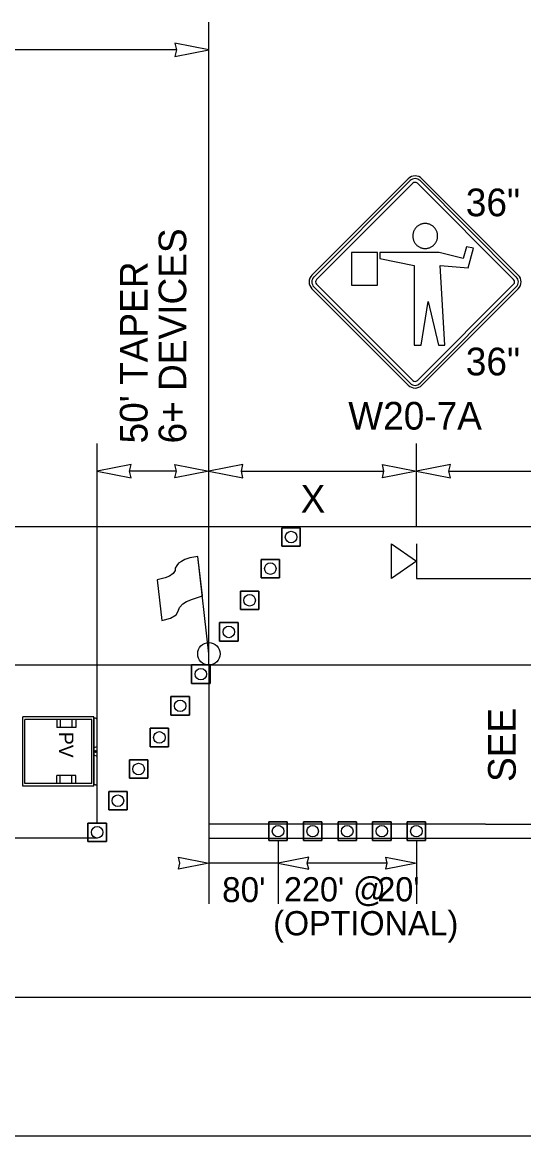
# Model space of a CAD drawing. Extents: x 99999.1 to 100095.7, y 99995 to 100010.7.
# Drawn here: x 100050.933 to 100052.384, y 100005.732 to 100008.949 of the extents above; entities that cross this region are included whole.
import ezdxf

# ---------------------------------------------------------------- set-up
doc = ezdxf.new("R2010")
doc.units = 0
for name, color, linetype in [('RD_ED_ShoulderPavedEdge', 7, 'Continuous'), ('RD_MK_LineDblYellowCenter', 7, 'Continuous'), ('RD_MK_LineEdgeWhite', 7, 'Continuous'), ('RD_MK_LineNoPass', 7, 'Continuous'), ('RD_MK_LineSkipCenter', 7, 'Continuous'), ('TR_SN_ConstructionSigns', 7, 'Continuous'), ('TR_WZ_FlaggingStation', 7, 'Continuous'), ('TR_WZ_PortableSignMountBlk-Org', 7, 'Continuous'), ('TR_WZ_ProtectiveVehicle', 7, 'Continuous'), ('TR_WZ_TrafficCone', 7, 'Continuous'), ('TR_WZ_WorkZoneDetails', 7, 'Continuous'), ('TR_WZ_WorkZoneTextCurrent', 7, 'Continuous')]:
    doc.layers.add(name, color=color, linetype=linetype)

msp = doc.modelspace()

# ---------------------------------------------------------------- linework, layer by layer
at = {"layer": 'RD_ED_ShoulderPavedEdge'}
for p, q in [((100040.1076, 100007.4923), (100055.6424, 100007.4923)), ((100040.1076, 100005.7323), (100055.6424, 100005.7323))]:
    msp.add_line(p, q, dxfattribs=at)
at = {"layer": 'RD_MK_LineDblYellowCenter'}
for p, q in [((100052.2733, 100006.6323), (100055.6631, 100006.6323)), ((100052.2733, 100006.5923), (100055.6218, 100006.5923))]:
    msp.add_line(p, q, dxfattribs=at)
at = {"layer": 'RD_MK_LineEdgeWhite'}
for p, q in [((100040.1076, 100007.0923), (100055.6424, 100007.0923)), ((100040.1076, 100006.1323), (100055.6424, 100006.1323))]:
    msp.add_line(p, q, dxfattribs=at)
at = {"layer": 'RD_MK_LineNoPass'}
msp.add_line((100051.4733, 100006.5923), (100052.2733, 100006.5923), dxfattribs=at)
at = {"layer": 'RD_MK_LineSkipCenter'}
for points in [[(100052.2733, 100006.6323), (100051.4733, 100006.6323)], [(100051.15, 100006.5923), (100043.4767, 100006.5923)]]:
    msp.add_lwpolyline(points, dxfattribs=at)
at = {"layer": 'TR_SN_ConstructionSigns'}
for p, q in [((100052.0497, 100008.4972), (100051.7713, 100008.2188)), ((100052.3679, 100008.2188), (100052.0895, 100008.4972)), ((100052.0552, 100008.4917), (100051.7768, 100008.2132)), ((100051.7845, 100008.2055), (100052.063, 100008.4839)), ((100052.0762, 100008.4839), (100052.3546, 100008.2055)), ((100052.3624, 100008.2132), (100052.0839, 100008.4917)), ((100052.0921, 100008.367), (100052.0902, 100008.3666)), ((100052.094, 100008.3673), (100052.0921, 100008.367)), ((100052.0959, 100008.3675), (100052.094, 100008.3673)), ((100052.0978, 100008.3676), (100052.0959, 100008.3675)), ((100052.0997, 100008.3676), (100052.0978, 100008.3676)), ((100052.1016, 100008.3675), (100052.0997, 100008.3676)), ((100052.1036, 100008.3673), (100052.1016, 100008.3675)), ((100052.1054, 100008.367), (100052.1036, 100008.3673)), ((100052.1073, 100008.3666), (100052.1054, 100008.367)), ((100052.063, 100008.3354), (100052.0628, 100008.3335)), ((100052.0632, 100008.3373), (100052.063, 100008.3354)), ((100052.0636, 100008.3392), (100052.0632, 100008.3373)), ((100052.064, 100008.3411), (100052.0636, 100008.3392)), ((100052.0646, 100008.3429), (100052.064, 100008.3411)), ((100052.0652, 100008.3447), (100052.0646, 100008.3429)), ((100052.066, 100008.3465), (100052.0652, 100008.3447)), ((100052.0668, 100008.3482), (100052.066, 100008.3465)), ((100052.0677, 100008.3499), (100052.0668, 100008.3482)), ((100052.0688, 100008.3516), (100052.0677, 100008.3499)), ((100052.0698, 100008.3531), (100052.0688, 100008.3516)), ((100052.071, 100008.3546), (100052.0698, 100008.3531)), ((100052.0723, 100008.3561), (100052.071, 100008.3546)), ((100052.0737, 100008.3574), (100052.0723, 100008.3561)), ((100052.075, 100008.3587), (100052.0737, 100008.3574)), ((100052.0765, 100008.3599), (100052.075, 100008.3587)), ((100052.078, 100008.3611), (100052.0765, 100008.3599)), ((100052.0797, 100008.3621), (100052.078, 100008.3611)), ((100052.0813, 100008.3631), (100052.0797, 100008.3621)), ((100052.083, 100008.364), (100052.0813, 100008.3631)), ((100052.0847, 100008.3648), (100052.083, 100008.364)), ((100052.0865, 100008.3655), (100052.0847, 100008.3648)), ((100052.0884, 100008.3661), (100052.0865, 100008.3655)), ((100052.0902, 100008.3666), (100052.0884, 100008.3661)), ((100052.1091, 100008.3661), (100052.1073, 100008.3666)), ((100052.111, 100008.3655), (100052.1091, 100008.3661)), ((100052.1128, 100008.3648), (100052.111, 100008.3655)), ((100052.1145, 100008.364), (100052.1128, 100008.3648)), ((100052.1162, 100008.3631), (100052.1145, 100008.364)), ((100052.1179, 100008.3621), (100052.1162, 100008.3631)), ((100052.1195, 100008.3611), (100052.1179, 100008.3621)), ((100052.121, 100008.3599), (100052.1195, 100008.3611)), ((100052.1225, 100008.3587), (100052.121, 100008.3599)), ((100052.1239, 100008.3574), (100052.1225, 100008.3587)), ((100052.1252, 100008.3561), (100052.1239, 100008.3574)), ((100052.1265, 100008.3546), (100052.1252, 100008.3561)), ((100052.1276, 100008.3531), (100052.1265, 100008.3546)), ((100052.1288, 100008.3516), (100052.1276, 100008.3531)), ((100052.1298, 100008.3499), (100052.1288, 100008.3516)), ((100052.1307, 100008.3482), (100052.1298, 100008.3499)), ((100052.1315, 100008.3465), (100052.1307, 100008.3482)), ((100052.1323, 100008.3447), (100052.1315, 100008.3465)), ((100052.133, 100008.3429), (100052.1323, 100008.3447)), ((100052.1335, 100008.3411), (100052.133, 100008.3429)), ((100052.134, 100008.3392), (100052.1335, 100008.3411)), ((100052.1343, 100008.3373), (100052.134, 100008.3392)), ((100052.1346, 100008.3354), (100052.1343, 100008.3373)), ((100052.1347, 100008.3335), (100052.1346, 100008.3354)), ((100052.0628, 100008.3335), (100052.0628, 100008.3316)), ((100052.0628, 100008.3316), (100052.0628, 100008.3297)), ((100052.0628, 100008.3297), (100052.063, 100008.3278)), ((100052.063, 100008.3278), (100052.0632, 100008.3259)), ((100052.0632, 100008.3259), (100052.0636, 100008.324)), ((100052.0636, 100008.324), (100052.064, 100008.3221)), ((100052.064, 100008.3221), (100052.0646, 100008.3203)), ((100052.0646, 100008.3203), (100052.0652, 100008.3185)), ((100052.0652, 100008.3185), (100052.066, 100008.3167)), ((100052.066, 100008.3167), (100052.0668, 100008.315)), ((100052.0668, 100008.315), (100052.0677, 100008.3133)), ((100052.0677, 100008.3133), (100052.0688, 100008.3117)), ((100052.0688, 100008.3117), (100052.0698, 100008.3101)), ((100052.0698, 100008.3101), (100052.071, 100008.3086)), ((100052.071, 100008.3086), (100052.0723, 100008.3072)), ((100052.0723, 100008.3072), (100052.0737, 100008.3058)), ((100052.0737, 100008.3058), (100052.075, 100008.3045)), ((100052.075, 100008.3045), (100052.0765, 100008.3033)), ((100052.0765, 100008.3033), (100052.078, 100008.3021)), ((100052.1195, 100008.3021), (100052.121, 100008.3033)), ((100052.121, 100008.3033), (100052.1225, 100008.3045)), ((100052.1225, 100008.3045), (100052.1239, 100008.3058)), ((100052.1239, 100008.3058), (100052.1252, 100008.3072)), ((100052.1252, 100008.3072), (100052.1265, 100008.3086)), ((100052.1265, 100008.3086), (100052.1276, 100008.3101)), ((100052.1276, 100008.3101), (100052.1288, 100008.3117)), ((100052.1288, 100008.3117), (100052.1298, 100008.3133)), ((100052.1298, 100008.3133), (100052.1307, 100008.315)), ((100052.1307, 100008.315), (100052.1315, 100008.3167)), ((100052.1315, 100008.3167), (100052.1323, 100008.3185)), ((100052.1323, 100008.3185), (100052.133, 100008.3203)), ((100052.133, 100008.3203), (100052.1335, 100008.3221)), ((100052.1335, 100008.3221), (100052.134, 100008.324)), ((100052.134, 100008.324), (100052.1343, 100008.3259)), ((100052.1343, 100008.3259), (100052.1346, 100008.3278)), ((100052.1346, 100008.3278), (100052.1347, 100008.3297)), ((100052.1348, 100008.3316), (100052.1347, 100008.3335)), ((100052.1347, 100008.3297), (100052.1348, 100008.3316)), ((100051.8853, 100008.2843), (100051.8853, 100008.1896)), ((100051.9607, 100008.2843), (100051.8853, 100008.2843)), ((100051.9607, 100008.1896), (100051.9607, 100008.2843)), ((100052.139, 100008.2843), (100051.9677, 100008.2843)), ((100051.9677, 100008.2843), (100051.9677, 100008.2662)), ((100052.078, 100008.3021), (100052.0797, 100008.3011)), ((100052.0797, 100008.3011), (100052.0813, 100008.3001)), ((100052.0813, 100008.3001), (100052.083, 100008.2992)), ((100052.083, 100008.2992), (100052.0847, 100008.2984)), ((100052.0847, 100008.2984), (100052.0865, 100008.2977)), ((100052.0865, 100008.2977), (100052.0884, 100008.2971)), ((100052.0884, 100008.2971), (100052.0902, 100008.2966)), ((100052.0902, 100008.2966), (100052.0921, 100008.2962)), ((100052.0921, 100008.2962), (100052.094, 100008.2959)), ((100052.094, 100008.2959), (100052.0959, 100008.2957)), ((100052.0959, 100008.2957), (100052.0978, 100008.2956)), ((100052.0978, 100008.2956), (100052.0997, 100008.2956)), ((100052.0997, 100008.2956), (100052.1016, 100008.2957)), ((100052.1016, 100008.2957), (100052.1036, 100008.2959)), ((100052.1036, 100008.2959), (100052.1054, 100008.2962)), ((100052.1054, 100008.2962), (100052.1073, 100008.2966)), ((100052.1073, 100008.2966), (100052.1091, 100008.2971)), ((100052.1091, 100008.2971), (100052.111, 100008.2977)), ((100052.111, 100008.2977), (100052.1128, 100008.2984)), ((100052.1128, 100008.2984), (100052.1145, 100008.2992)), ((100052.1145, 100008.2992), (100052.1162, 100008.3001)), ((100052.1162, 100008.3001), (100052.1179, 100008.3011)), ((100052.1179, 100008.3011), (100052.1195, 100008.3021)), ((100052.2086, 100008.2671), (100052.139, 100008.2843)), ((100052.2183, 100008.3), (100052.2086, 100008.2671)), ((100052.2382, 100008.2964), (100052.2183, 100008.3)), ((100052.2232, 100008.2396), (100052.2382, 100008.2964)), ((100051.9677, 100008.2662), (100052.0672, 100008.2464)), ((100052.0672, 100008.2464), (100052.0672, 100008.0161)), ((100052.1553, 100008.0161), (100052.1422, 100008.2465)), ((100052.1422, 100008.2465), (100052.2232, 100008.2396)), ((100051.7713, 100008.179), (100052.0497, 100007.9006)), ((100051.7768, 100008.1845), (100052.0552, 100007.9061)), ((100052.063, 100007.9138), (100051.7845, 100008.1923)), ((100051.8853, 100008.1896), (100051.9607, 100008.1896)), ((100052.3546, 100008.1923), (100052.0762, 100007.9138)), ((100052.0839, 100007.9061), (100052.3624, 100008.1845)), ((100052.0895, 100007.9006), (100052.3679, 100008.179)), ((100052.0874, 100008.0161), (100052.107, 100008.1428)), ((100052.107, 100008.1428), (100052.1373, 100008.0161)), ((100052.0672, 100008.0161), (100052.0874, 100008.0161)), ((100052.1373, 100008.0161), (100052.1553, 100008.0161))]:
    msp.add_line(p, q, dxfattribs=at)
for centre, radius, start, end in [((100052.0696, 100008.4773), 0.0281, 45, 135), ((100052.0696, 100008.4773), 0.0203, 45, 135), ((100052.0696, 100008.4773), 0.00937, 45, 135), ((100051.7912, 100008.1989), 0.0281, 135, 225), ((100051.7912, 100008.1989), 0.0203, 135, 225), ((100052.348, 100008.1989), 0.0203, 315, 45), ((100052.348, 100008.1989), 0.0281, 315, 45), ((100051.7912, 100008.1989), 0.00937, 135, 225), ((100052.348, 100008.1989), 0.00937, 315, 45), ((100052.0696, 100007.9205), 0.0281, 225, 315), ((100052.0696, 100007.9205), 0.0203, 225, 315), ((100052.0696, 100007.9205), 0.00937, 225, 315)]:
    msp.add_arc(centre, radius, start, end, dxfattribs=at)
at = {"layer": 'TR_WZ_FlaggingStation'}
for p, q in [((100051.4543, 100007.2917), (100051.4413, 100007.4061)), ((100051.4733, 100007.1248), (100051.4413, 100007.4058)), ((100051.3233, 100007.3383), (100051.3366, 100007.2211)), ((100051.4543, 100007.2917), (100051.4543, 100007.2917))]:
    msp.add_line(p, q, dxfattribs=at)
for points in [[(100051.4413, 100007.4061), (100051.4355, 100007.4048), (100051.4177, 100007.4014), (100051.4039, 100007.3972), (100051.3942, 100007.3911), (100051.3857, 100007.3864), (100051.38, 100007.3796), (100051.3757, 100007.3717), (100051.3752, 100007.3655), (100051.3698, 100007.3563), (100051.359, 100007.3489), (100051.3466, 100007.3437), (100051.3233, 100007.3383)], [(100051.3366, 100007.2211), (100051.3448, 100007.2225), (100051.3624, 100007.2271), (100051.3781, 100007.2376), (100051.3846, 100007.2482), (100051.3885, 100007.2585), (100051.3976, 100007.2694), (100051.4086, 100007.2756), (100051.4259, 100007.2827), (100051.4543, 100007.2917)]]:
    msp.add_lwpolyline(points, dxfattribs=at)
msp.add_circle((100051.4733, 100007.1248), 0.0325, dxfattribs=at)
at = {"layer": 'TR_WZ_PortableSignMountBlk-Org'}
msp.add_line((100052.0733, 100007.4422), (100052.0733, 100007.3422), dxfattribs=at)
msp.add_lwpolyline([(100052.0733, 100007.3923), (100052.0015, 100007.3422), (100052.0015, 100007.4422)], close=True, dxfattribs=at)
at = {"layer": 'TR_WZ_ProtectiveVehicle'}
for p, q in [((100051.1404, 100006.9423), (100050.9347, 100006.9423)), ((100050.9347, 100006.7423), (100050.9347, 100006.9423)), ((100051.1346, 100006.9344), (100050.9405, 100006.9344)), ((100050.9405, 100006.7503), (100050.9405, 100006.9344)), ((100051.0332, 100006.9344), (100051.0332, 100006.9113)), ((100051.0432, 100006.9344), (100051.0432, 100006.9113)), ((100051.0772, 100006.9344), (100051.0772, 100006.9113)), ((100051.0882, 100006.9344), (100051.0882, 100006.9113)), ((100051.1346, 100006.7503), (100051.1346, 100006.9344)), ((100051.1404, 100006.7423), (100051.1404, 100006.9423)), ((100051.1456, 100006.939), (100051.1411, 100006.939)), ((100051.1411, 100006.7456), (100051.1411, 100006.939)), ((100051.15, 100006.7517), (100051.15, 100006.9329)), ((100051.0882, 100006.9113), (100051.0332, 100006.9113)), ((100051.15, 100006.8564), (100051.1411, 100006.8527)), ((100051.15, 100006.8282), (100051.1411, 100006.832)), ((100051.1476, 100006.8423), (100051.1435, 100006.8423)), ((100051.1456, 100006.8395), (100051.1456, 100006.8451)), ((100051.0882, 100006.7733), (100051.0332, 100006.7733)), ((100051.0332, 100006.7503), (100051.0332, 100006.7733)), ((100051.0432, 100006.7503), (100051.0432, 100006.7733)), ((100051.0772, 100006.7503), (100051.0772, 100006.7733)), ((100051.0882, 100006.7503), (100051.0882, 100006.7733)), ((100051.1404, 100006.7423), (100050.9347, 100006.7423)), ((100051.1346, 100006.7503), (100050.9405, 100006.7503)), ((100051.1456, 100006.7456), (100051.1411, 100006.7456))]:
    msp.add_line(p, q, dxfattribs=at)
for centre, major_axis, start_param, end_param in [((100051.1456, 100006.9329), (0, 0.0061), 4.712389, 6.283185), ((100051.1456, 100006.7517), (0, -0.0061), 6.283185, 7.853982)]:
    msp.add_ellipse(centre, major_axis=major_axis, ratio=0.73155, start_param=start_param, end_param=end_param, dxfattribs=at)
msp.add_ellipse((100051.1456, 100006.8423), major_axis=(0, 0.00282), ratio=0.73155, dxfattribs=at)
at = {"layer": 'TR_WZ_TrafficCone'}
for points in [[(100051.6843, 100007.4886), (100051.7376, 100007.4886), (100051.7376, 100007.4352), (100051.6843, 100007.4352), (100051.6843, 100007.4886)], [(100051.6843, 100007.4352), (100051.7376, 100007.4352), (100051.7376, 100007.4886), (100051.6843, 100007.4886), (100051.6843, 100007.4352)], [(100051.6243, 100007.3972), (100051.6776, 100007.3972), (100051.6776, 100007.3439), (100051.6243, 100007.3439), (100051.6243, 100007.3972)], [(100051.6243, 100007.3439), (100051.6776, 100007.3439), (100051.6776, 100007.3972), (100051.6243, 100007.3972), (100051.6243, 100007.3439)], [(100051.5643, 100007.3059), (100051.6176, 100007.3059), (100051.6176, 100007.2526), (100051.5643, 100007.2526), (100051.5643, 100007.3059)], [(100051.5643, 100007.2526), (100051.6176, 100007.2526), (100051.6176, 100007.3059), (100051.5643, 100007.3059), (100051.5643, 100007.2526)], [(100051.5043, 100007.2146), (100051.5576, 100007.2146), (100051.5576, 100007.1612), (100051.5043, 100007.1612), (100051.5043, 100007.2146)], [(100051.5043, 100007.1612), (100051.5576, 100007.1612), (100051.5576, 100007.2146), (100051.5043, 100007.2146), (100051.5043, 100007.1612)], [(100051.4766, 100007.0923), (100051.4233, 100007.0923), (100051.4233, 100007.039), (100051.4766, 100007.039), (100051.4766, 100007.0923)], [(100051.4766, 100007.039), (100051.4233, 100007.039), (100051.4233, 100007.0923), (100051.4766, 100007.0923), (100051.4766, 100007.039)], [(100051.4166, 100007.001), (100051.3633, 100007.001), (100051.3633, 100006.9477), (100051.4166, 100006.9477), (100051.4166, 100007.001)], [(100051.4166, 100006.9477), (100051.3633, 100006.9477), (100051.3633, 100007.001), (100051.4166, 100007.001), (100051.4166, 100006.9477)], [(100051.3566, 100006.9097), (100051.3033, 100006.9097), (100051.3033, 100006.8563), (100051.3566, 100006.8563), (100051.3566, 100006.9097)], [(100051.3566, 100006.8563), (100051.3033, 100006.8563), (100051.3033, 100006.9097), (100051.3566, 100006.9097), (100051.3566, 100006.8563)], [(100051.2966, 100006.8183), (100051.2433, 100006.8183), (100051.2433, 100006.765), (100051.2966, 100006.765), (100051.2966, 100006.8183)], [(100051.2966, 100006.765), (100051.2433, 100006.765), (100051.2433, 100006.8183), (100051.2966, 100006.8183), (100051.2966, 100006.765)], [(100051.2366, 100006.727), (100051.1833, 100006.727), (100051.1833, 100006.6737), (100051.2366, 100006.6737), (100051.2366, 100006.727)], [(100051.2366, 100006.6737), (100051.1833, 100006.6737), (100051.1833, 100006.727), (100051.2366, 100006.727), (100051.2366, 100006.6737)], [(100051.1766, 100006.6357), (100051.1233, 100006.6357), (100051.1233, 100006.5823), (100051.1766, 100006.5823), (100051.1766, 100006.6357)], [(100051.1766, 100006.5823), (100051.1233, 100006.5823), (100051.1233, 100006.6357), (100051.1766, 100006.6357), (100051.1766, 100006.5823)], [(100051.7, 100006.639), (100051.6467, 100006.639), (100051.6467, 100006.5857), (100051.7, 100006.5857), (100051.7, 100006.639)], [(100051.7, 100006.5857), (100051.6467, 100006.5857), (100051.6467, 100006.639), (100051.7, 100006.639), (100051.7, 100006.5857)], [(100051.8, 100006.639), (100051.7467, 100006.639), (100051.7467, 100006.5857), (100051.8, 100006.5857), (100051.8, 100006.639)], [(100051.8, 100006.5857), (100051.7467, 100006.5857), (100051.7467, 100006.639), (100051.8, 100006.639), (100051.8, 100006.5857)], [(100051.9, 100006.639), (100051.8467, 100006.639), (100051.8467, 100006.5857), (100051.9, 100006.5857), (100051.9, 100006.639)], [(100051.9, 100006.5857), (100051.8467, 100006.5857), (100051.8467, 100006.639), (100051.9, 100006.639), (100051.9, 100006.5857)], [(100052, 100006.639), (100051.9467, 100006.639), (100051.9467, 100006.5857), (100052, 100006.5857), (100052, 100006.639)], [(100052, 100006.5857), (100051.9467, 100006.5857), (100051.9467, 100006.639), (100052, 100006.639), (100052, 100006.5857)], [(100052.1, 100006.639), (100052.0467, 100006.639), (100052.0467, 100006.5857), (100052.1, 100006.5857), (100052.1, 100006.639)], [(100052.1, 100006.5857), (100052.0467, 100006.5857), (100052.0467, 100006.639), (100052.1, 100006.639), (100052.1, 100006.5857)]]:
    msp.add_lwpolyline(points, dxfattribs=at)
for centre in [(100051.7109, 100007.4619), (100051.6509, 100007.3706), (100051.5909, 100007.2792), (100051.5309, 100007.1879), (100051.45, 100007.0657), (100051.39, 100006.9743), (100051.33, 100006.883), (100051.27, 100006.7917), (100051.21, 100006.7003), (100051.15, 100006.609), (100051.6733, 100006.6123), (100051.7733, 100006.6123), (100051.8733, 100006.6123), (100051.9733, 100006.6123), (100052.0733, 100006.6123)]:
    msp.add_circle(centre, 0.0167, dxfattribs=at)
at = {"layer": 'TR_WZ_WorkZoneDetails'}
for p, q in [((100051.4733, 100007.0923), (100051.4733, 100008.9491)), ((100051.3796, 100008.8691), (100044.3704, 100008.8691)), ((100051.15, 100006.6357), (100051.15, 100007.7323)), ((100052.0733, 100007.4923), (100052.0733, 100007.7323)), ((100051.3796, 100007.6523), (100051.2437, 100007.6523)), ((100051.5671, 100007.6523), (100051.9796, 100007.6523)), ((100052.1671, 100007.6523), (100052.7296, 100007.6523)), ((100052.0733, 100007.3422), (100055.1733, 100007.3422)), ((100051.4733, 100007.0923), (100051.4733, 100006.4023)), ((100051.6733, 100006.5857), (100051.6733, 100006.4023)), ((100052.0733, 100006.5857), (100052.0733, 100006.4023)), ((100051.6733, 100006.5193), (100051.4733, 100006.5193)), ((100051.989, 100006.5193), (100051.7577, 100006.5193))]:
    msp.add_line(p, q, dxfattribs=at)
for points in [[(100051.4733, 100008.8691), (100051.3751, 100008.8884), (100051.3796, 100008.8691), (100051.3751, 100008.8498)], [(100051.15, 100007.6523), (100051.2483, 100007.6331), (100051.2437, 100007.6523), (100051.2483, 100007.6716)], [(100051.4733, 100007.6523), (100051.3751, 100007.6331), (100051.3796, 100007.6523), (100051.3751, 100007.6716)], [(100051.4733, 100007.6523), (100051.5716, 100007.6331), (100051.5671, 100007.6523), (100051.5716, 100007.6716)], [(100052.0733, 100007.6523), (100051.9751, 100007.6331), (100051.9796, 100007.6523), (100051.9751, 100007.6716)], [(100052.0733, 100007.6523), (100052.1716, 100007.6331), (100052.1671, 100007.6523), (100052.1716, 100007.6716)], [(100051.4733, 100006.5193), (100051.3849, 100006.502), (100051.389, 100006.5193), (100051.3849, 100006.5367)], [(100051.6733, 100006.5193), (100051.7618, 100006.502), (100051.7577, 100006.5193), (100051.7618, 100006.5367)], [(100052.0733, 100006.5193), (100051.9849, 100006.502), (100051.989, 100006.5193), (100051.9849, 100006.5367)]]:
    msp.add_lwpolyline(points, close=True, dxfattribs=at)

# ---------------------------------------------------------------- texts
at = {"layer": 'TR_SN_ConstructionSigns'}
for s, p in [('36"', (100052.2163, 100008.3887)), ('36"', (100052.2163, 100007.9291)), ('W20-7A', (100051.8763, 100007.7723))]:
    msp.add_text(s, height=0.08, rotation=360, dxfattribs=at).set_placement(p)
at = {"layer": 'TR_WZ_ProtectiveVehicle'}
msp.add_text('PV', height=0.04175, rotation=270, dxfattribs=at).set_placement((100051.0398, 100006.899))
at = {"layer": 'TR_WZ_WorkZoneDetails'}
msp.add_text('SEE', height=0.08, rotation=90, dxfattribs=at).set_placement((100052.3608, 100006.7544))
at = {"layer": 'TR_WZ_WorkZoneTextCurrent'}
for s, p in [('6+ DEVICES', (100051.4077, 100007.7323)), ("50' TAPER", (100051.2957, 100007.7323))]:
    msp.add_text(s, height=0.08, rotation=90, dxfattribs=at).set_placement(p)
for s, height, p in [('X', 0.08, (100051.7386, 100007.5323)), ("80'", 0.072, (100051.5114, 100006.4073)), ("220' @", 0.07, (100051.6903, 100006.4093)), ("20'", 0.07, (100051.9604, 100006.4093)), ('(OPTIONAL)', 0.07, (100051.659, 100006.3113))]:
    msp.add_text(s, height=height, dxfattribs=at).set_placement(p)

doc.saveas('drawing.dxf')
